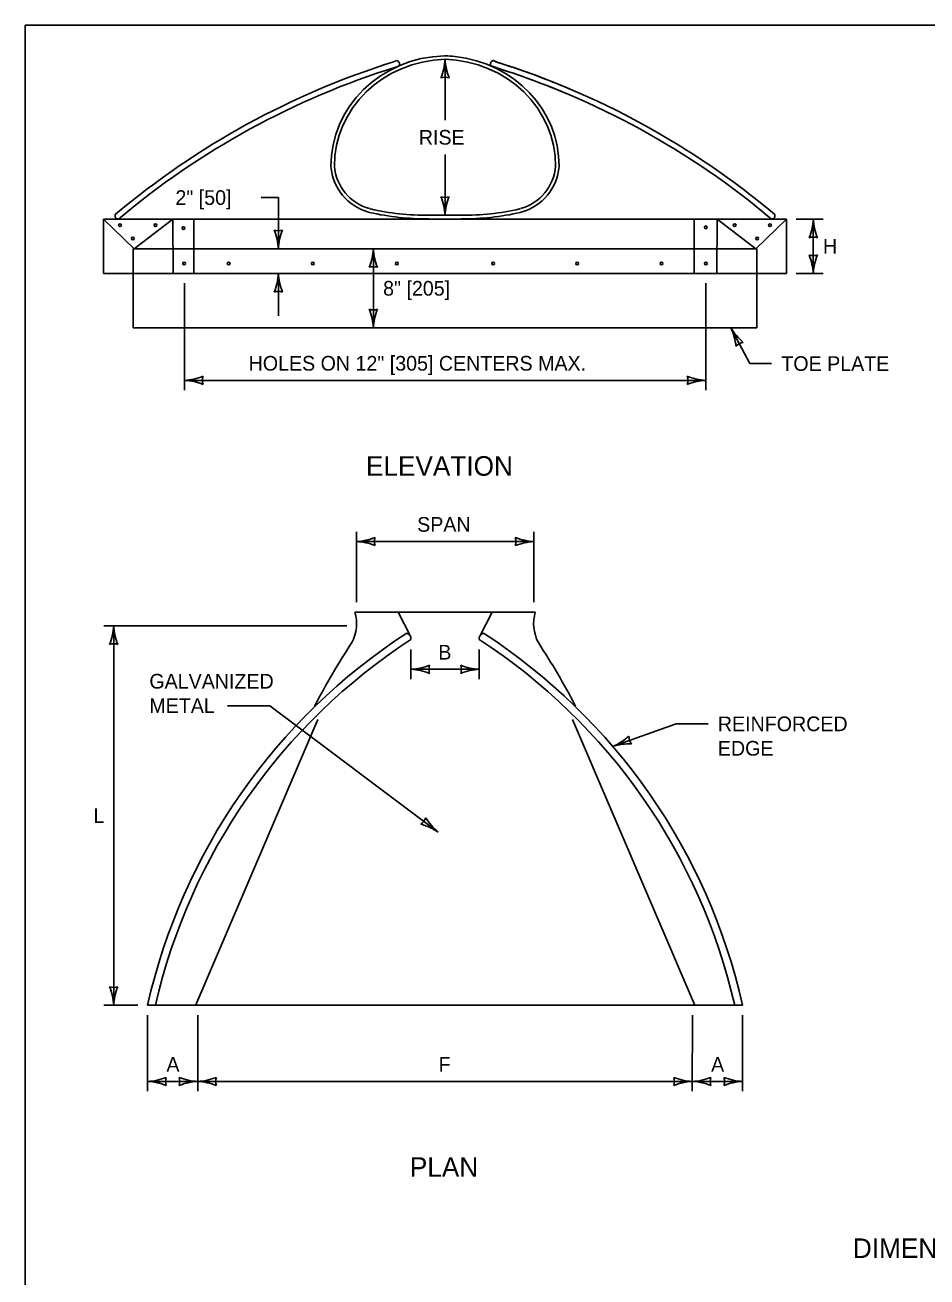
# Model space of a CAD drawing. Extents: x 49991.4 to 50021, y 49987.6 to 50011.4.
# Drawn here: x 49999.38 to 50003.07, y 49993.88 to 49999 of the extents above; entities that cross this region are included whole.
import ezdxf

# ---------------------------------------------------------------- set-up
doc = ezdxf.new("R2010")
doc.units = 0
for name, color, linetype in [('Level 1', 7, 'Continuous'), ('Level 2', 7, 'Continuous'), ('Level 3', 7, 'Continuous'), ('Level 4', 7, 'Continuous')]:
    doc.layers.add(name, color=color, linetype=linetype)

msp = doc.modelspace()

# ---------------------------------------------------------------- linework, layer by layer
at = {"layer": 'Level 1'}
for p, q in [((50000.8894, 49998.8486), (50000.9029, 49998.854)), ((50001.098, 49998.8735), (50001.1016, 49998.8735)), ((50001.3107, 49998.8483), (50001.2974, 49998.8541)), ((50001.3107, 49998.8483), (50001.2974, 49998.8541)), ((50001.3111, 49998.8483), (50001.298, 49998.8541)), ((50001.3111, 49998.8483), (50001.298, 49998.8541)), ((50000.8999, 49998.8274), (50000.9126, 49998.833)), ((50001.3008, 49998.8276), (50001.2877, 49998.833)), ((50001.3012, 49998.8276), (50001.2883, 49998.833)), ((50000.7879, 49998.2341), (50000.792, 49998.233)), ((50000.7924, 49998.2481), (50000.7965, 49998.2466)), ((50001.408, 49998.2481), (50001.404, 49998.2466)), ((50001.4122, 49998.2341), (50001.408, 49998.233)), ((49999.7044, 49997.9828), (49999.7044, 49998.2055)), ((49999.7044, 49998.2055), (50002.4958, 49998.2055)), ((49999.7044, 49998.2055), (49999.8291, 49998.0843)), ((49999.8291, 49998.0843), (49999.9875, 49998.2055)), ((49999.9875, 49998.2055), (49999.9887, 49997.9839)), ((50001.1005, 49998.221), (50001.0338, 49998.221)), ((50001.0341, 49998.207), (50001.1005, 49998.2055)), ((50001.6126, 49998.2055), (50001.0611, 49998.2055)), ((50001.1659, 49998.207), (50001.0999, 49998.2055)), ((50001.1005, 49998.221), (50001.1667, 49998.221)), ((50002.2128, 49998.2055), (50002.212, 49997.9839)), ((50002.3716, 49998.0843), (50002.2128, 49998.2055)), ((50002.4958, 49998.2055), (50002.3716, 49998.0843)), ((50002.4958, 49998.2055), (50002.4958, 49997.9828)), ((49999.7044, 49997.9828), (50002.4958, 49997.9828)), ((50001.1005, 49996.5982), (50000.7319, 49996.5982)), ((50000.9085, 49996.5982), (50000.9587, 49996.5001)), ((50001.1005, 49996.5982), (50001.4694, 49996.5982)), ((50001.293, 49996.5982), (50001.2424, 49996.5001)), ((50000.0815, 49994.9916), (50000.5799, 49996.1588)), ((50002.1208, 49994.9927), (50001.6209, 49996.1588)), ((49999.9163, 49994.9897), (49999.8846, 49994.9897)), ((50001.1005, 49994.9897), (49999.8846, 49994.9897)), ((50001.1005, 49994.9897), (50002.2845, 49994.9897)), ((50002.2854, 49994.9897), (50002.3169, 49994.9897))]:
    msp.add_line(p, q, dxfattribs=at)
msp.add_lwpolyline([(49999.3835, 49998.9992), (50016.7501, 49998.9992), (50016.7501, 49987.7988), (49999.3835, 49987.7988)], close=True, dxfattribs=at)
for centre in [(49999.7717, 49998.1811), (49999.9163, 49998.1811), (50002.1661, 49998.1718), (50002.2843, 49998.1811), (50002.4289, 49998.1811), (49999.8241, 49998.1265), (50000.031, 49998.1687), (50002.3766, 49998.1265), (50000.0338, 49998.0234), (50000.2158, 49998.0234), (50000.5597, 49998.0234), (50000.9036, 49998.0234), (50001.297, 49998.0234), (50001.6409, 49998.0234), (50001.9848, 49998.0234), (50002.1669, 49998.0234)]:
    msp.add_circle(centre, 0.00557, dxfattribs=at)
for centre, radius, start, end in [((50001.8796, 49995.6986), 3.3019, 107.4492, 130.0758), ((50000.8998, 49998.8398), 0.0145, 331.9431, 77.9332), ((50001.3006, 49998.8399), 0.0145, 102.0651, 208.4686), ((50001.3009, 49998.8399), 0.0145, 102.0651, 208.4686), ((50000.3179, 49995.6902), 3.3102, 66.9754, 72.6075), ((50000.3183, 49995.6902), 3.3102, 49.9808, 72.6075), ((50001.8821, 49995.6895), 3.2881, 107.3819, 130.0762), ((50000.3179, 49995.6902), 3.2878, 66.809, 72.6075), ((50000.3183, 49995.6902), 3.2878, 49.9128, 72.6075), ((50000.843, 49998.4366), 0.2097, 184.3908, 254.795), ((50000.843, 49998.4366), 0.1951, 184.3908, 254.795), ((50001.3576, 49998.4366), 0.1951, 285.205, 355.6092), ((50001.3573, 49998.4366), 0.2097, 285.205, 355.6092), ((50001.0191, 49999.2007), 0.994, 256.7971, 270.8603), ((50001.0191, 49999.2007), 0.9795, 256.7971, 270.8603), ((50001.1812, 49999.2007), 0.994, 269.1397, 283.2029), ((50001.1815, 49999.2007), 0.9795, 269.1397, 283.2029), ((49999.7647, 49998.2184), 0.0129, 148.2499, 272.1953), ((50002.4359, 49998.2184), 0.0129, 267.8624, 31.8078), ((50002.4359, 49998.2184), 0.0129, 267.8624, 31.8078), ((50000.5723, 49996.551), 0.1664, 332.1165, 16.4834), ((50001.6289, 49996.551), 0.1664, 163.5166, 207.8835), ((50002.2857, 49994.4484), 2.4616, 123.0384, 167.2954), ((50002.2857, 49994.4484), 2.4302, 123.0384, 167.1285), ((50000.9383, 49996.4897), 0.0228, 349.5581, 76.5269), ((50001.2628, 49996.4897), 0.0228, 103.4731, 190.4419), ((49999.9155, 49994.4484), 2.4302, 12.8715, 56.9616), ((49999.9155, 49994.4484), 2.4616, 12.7046, 56.9616), ((50003.3267, 49994.7722), 3.1131, 146.8806, 152.4206), ((49998.8745, 49994.7722), 3.1131, 27.5794, 33.1194)]:
    msp.add_arc(centre, radius, start, end, dxfattribs=at)
for centre, major_axis, ratio, start_param, end_param in [((50001.1136, 49998.4255), (-0.4797, -0.0049), 0.934337, 4.735052, 6.283185), ((50001.1136, 49998.4255), (-0.4651, -0.0047), 0.932282, 4.731472, 6.283185), ((50001.087, 49998.4255), (0.4651, -0.0047), 0.932282, 0, 1.551713), ((50001.0867, 49998.4255), (0.4797, -0.0049), 0.934337, 1.467761, 1.549044), ((50001.0867, 49998.4255), (0.4797, -0.0049), 0.934337, 0, 1.467761)]:
    msp.add_ellipse(centre, major_axis=major_axis, ratio=ratio, start_param=start_param, end_param=end_param, dxfattribs=at)
at = {"layer": 'Level 3'}
for p, q in [((50001.1005, 49998.8589), (50001.1005, 49998.61)), ((50001.1005, 49998.47), (50001.1005, 49998.221)), ((50000.4192, 49998.2935), (50000.3493, 49998.2935)), ((50000.4192, 49998.2935), (50000.4192, 49998.0842)), ((50002.5358, 49998.2055), (50002.6456, 49998.2055)), ((50002.6056, 49998.2055), (50002.6056, 49997.9828)), ((50000.8073, 49998.0842), (50000.8073, 49997.7607)), ((50000.4192, 49997.9828), (50000.4192, 49997.8094)), ((50002.5358, 49997.9828), (50002.6456, 49997.9828)), ((50000.0354, 49997.9428), (50000.0354, 49997.5057)), ((50002.1667, 49997.9428), (50002.1667, 49997.5057)), ((50002.3458, 49997.6145), (50002.2692, 49997.7607)), ((50002.3458, 49997.6145), (50002.4352, 49997.6145)), ((50000.0354, 49997.5457), (50002.1667, 49997.5457)), ((50000.7381, 49996.6382), (50000.7381, 49996.9266)), ((50001.4633, 49996.6382), (50001.4633, 49996.9266)), ((50000.7381, 49996.8866), (50001.4633, 49996.8866)), ((50000.6984, 49996.542), (49999.7058, 49996.542)), ((49999.7458, 49994.9897), (49999.7458, 49996.542)), ((50000.961, 49996.4456), (50000.961, 49996.3239)), ((50001.2405, 49996.4456), (50001.2405, 49996.3239)), ((50000.961, 49996.3639), (50001.2405, 49996.3639)), ((50000.2111, 49996.2152), (50000.3842, 49996.2152)), ((50001.0725, 49995.6977), (50000.3842, 49996.2152)), ((50002.0455, 49996.1409), (50001.7856, 49996.0489)), ((50002.0455, 49996.1409), (50002.1757, 49996.1409)), ((49999.8444, 49994.9897), (49999.7058, 49994.9897)), ((49999.8847, 49994.9497), (49999.8847, 49994.6381)), ((50000.0894, 49994.9497), (50000.0894, 49994.6381)), ((50002.1114, 49994.9497), (50002.1112, 49994.6381)), ((50002.3168, 49994.9497), (50002.3165, 49994.6381)), ((49999.8847, 49994.6781), (50000.0894, 49994.6781)), ((50000.0894, 49994.6781), (50000.0894, 49994.6781)), ((50000.0894, 49994.6781), (50002.1112, 49994.6781)), ((50002.1112, 49994.6781), (50002.3166, 49994.6781))]:
    msp.add_line(p, q, dxfattribs=at)
for centre, radius, start, end in [((50000.8784, 49998.8681), 0.2223, 337.456, 357.6395), ((50001.3333, 49998.8704), 0.233, 182.8273, 202.0772), ((50001.1005, 49998.7307), 0.0548, 72.1388, 107.8612), ((50001.1005, 49998.3492), 0.0548, 252.1388, 287.8612), ((50000.8678, 49998.2095), 0.233, 2.8273, 22.0772), ((50001.3227, 49998.2119), 0.2223, 157.456, 177.6395), ((50002.3835, 49998.2147), 0.2223, 337.456, 357.6395), ((50002.8384, 49998.217), 0.233, 182.8273, 202.0772), ((50000.4192, 49998.2124), 0.0548, 252.1388, 287.8612), ((50000.1865, 49998.0727), 0.233, 2.8273, 22.0772), ((50000.6414, 49998.0751), 0.2223, 157.456, 177.6395), ((50002.6056, 49998.0773), 0.0548, 72.1388, 107.8612), ((50000.5852, 49998.0934), 0.2223, 337.456, 357.6395), ((50001.0401, 49998.0957), 0.233, 182.8273, 202.0772), ((50002.6056, 49998.111), 0.0548, 252.1388, 287.8612), ((50002.3729, 49997.9713), 0.233, 2.8273, 22.0772), ((50002.8278, 49997.9737), 0.2223, 157.456, 177.6395), ((50000.1971, 49997.992), 0.2223, 337.456, 357.6395), ((50000.652, 49997.9943), 0.233, 182.8273, 202.0772), ((50000.8073, 49997.956), 0.0548, 72.1388, 107.8612), ((50000.4192, 49997.8546), 0.0548, 72.1388, 107.8612), ((50000.8073, 49997.8889), 0.0548, 252.1388, 287.8612), ((50000.5746, 49997.7492), 0.233, 2.8273, 22.0772), ((50001.0295, 49997.7516), 0.2223, 157.456, 177.6395), ((50002.0682, 49997.6657), 0.2223, 5.1078, 25.2914), ((50002.47, 49997.8789), 0.233, 210.4791, 229.729), ((50002.3287, 49997.6471), 0.0548, 99.7907, 135.513), ((50000.0239, 49997.7784), 0.233, 272.8273, 292.0772), ((50000.1637, 49997.5457), 0.0548, 162.1388, 197.8612), ((50002.1759, 49997.7678), 0.2223, 247.456, 267.6395), ((50002.0385, 49997.5457), 0.0548, 342.1388, 17.8612), ((50000.0263, 49997.3236), 0.2223, 67.456, 87.6395), ((50002.1782, 49997.313), 0.233, 92.8273, 112.0772), ((50000.7266, 49997.1193), 0.233, 272.8273, 292.0772), ((50000.8664, 49996.8866), 0.0548, 162.1388, 197.8612), ((50001.4725, 49997.1088), 0.2223, 247.456, 267.6395), ((50001.3351, 49996.8866), 0.0548, 342.1388, 17.8612), ((50000.729, 49996.6645), 0.2223, 67.456, 87.6395), ((50001.4748, 49996.6539), 0.233, 92.8273, 112.0772), ((49999.5237, 49996.5512), 0.2223, 337.456, 357.6395), ((49999.9786, 49996.5535), 0.233, 182.8273, 202.0772), ((49999.7458, 49996.4138), 0.0548, 72.1388, 107.8612), ((50000.9495, 49996.5966), 0.233, 272.8273, 292.0772), ((50000.9519, 49996.1418), 0.2223, 67.456, 87.6395), ((50001.0893, 49996.3639), 0.0548, 162.1388, 197.8612), ((50001.2497, 49996.5861), 0.2223, 247.456, 267.6395), ((50001.1123, 49996.3639), 0.0548, 342.1388, 17.8612), ((50001.252, 49996.1312), 0.233, 92.8273, 112.0772), ((50001.6971, 49996.2644), 0.233, 292.3235, 311.5734), ((50001.9065, 49996.0917), 0.0548, 181.6351, 217.3574), ((50001.8512, 49995.8365), 0.2223, 86.9522, 107.1358), ((50000.9701, 49995.7748), 0.0548, 305.2011, 340.9234), ((50000.9419, 49995.5048), 0.233, 55.8895, 75.1394), ((50001.2133, 49995.8698), 0.2223, 210.5182, 230.7018), ((49999.7458, 49995.1179), 0.0548, 252.1388, 287.8612), ((49999.5131, 49994.9782), 0.233, 2.8273, 22.0772), ((49999.968, 49994.9806), 0.2223, 157.456, 177.6395), ((49999.8732, 49994.9108), 0.233, 272.8273, 292.0772), ((50000.013, 49994.6781), 0.0548, 162.1388, 197.8612), ((50000.0986, 49994.9003), 0.2223, 247.456, 267.6395), ((49999.9612, 49994.6781), 0.0548, 342.1388, 17.8612), ((50000.0779, 49994.9108), 0.233, 272.8273, 292.0772), ((50000.2177, 49994.6781), 0.0548, 162.1388, 197.8612), ((50002.1204, 49994.9003), 0.2223, 247.456, 267.6395), ((50001.9831, 49994.6781), 0.0548, 342.1388, 17.8612), ((50002.0998, 49994.9108), 0.233, 272.8273, 292.0772), ((50002.2395, 49994.6781), 0.0548, 162.1388, 197.8612), ((50002.3257, 49994.9003), 0.2223, 247.456, 267.6395), ((50002.1884, 49994.6781), 0.0548, 342.1388, 17.8612), ((49999.8756, 49994.456), 0.2223, 67.456, 87.6395), ((50000.1009, 49994.4454), 0.233, 92.8273, 112.0772), ((50000.0803, 49994.456), 0.2223, 67.456, 87.6395), ((50002.1228, 49994.4454), 0.233, 92.8273, 112.0772), ((50002.1021, 49994.456), 0.2223, 67.456, 87.6395), ((50002.3281, 49994.4454), 0.233, 92.8273, 112.0772)]:
    msp.add_arc(centre, radius, start, end, dxfattribs=at)
at = {"layer": 'Level 4'}
for p, q in [((50000.073, 49998.2045), (50000.0736, 49997.9837)), ((50002.1188, 49998.2045), (50002.1194, 49997.9837)), ((49999.8256, 49997.7607), (49999.8256, 49998.0842)), ((49999.8256, 49998.0842), (50002.3746, 49998.0842)), ((50002.3746, 49997.7607), (50002.3746, 49998.0842)), ((49999.8256, 49997.7607), (50002.3746, 49997.7607))]:
    msp.add_line(p, q, dxfattribs=at)

# ---------------------------------------------------------------- texts
at = {"layer": 'Level 2'}
for s, height, p in [('RISE', 0.06, (50000.9933, 49998.51)), ('2" [50]', 0.06, (49999.9982, 49998.2635)), ('H', 0.06, (50002.6456, 49998.0642)), ('8" [205]', 0.06, (50000.8473, 49997.8924)), ('HOLES ON 12" [305] CENTERS MAX.', 0.06, (50000.2975, 49997.5857)), ('TOE PLATE', 0.06, (50002.4752, 49997.5845)), ('ELEVATION', 0.08, (50000.7773, 49997.1557)), ('SPAN', 0.06, (50000.9864, 49996.9266)), ('B', 0.06, (50001.073, 49996.4039)), ('GALVANIZED', 0.06, (49999.8917, 49996.2852)), ('METAL', 0.06, (49999.8917, 49996.1852)), ('REINFORCED', 0.06, (50002.2157, 49996.1109)), ('EDGE', 0.06, (50002.2157, 49996.0109)), ('L', 0.06, (49999.6635, 49995.7358)), ('A', 0.06, (49999.9613, 49994.7181)), ('F', 0.06, (50001.0742, 49994.7181)), ('A', 0.06, (50002.1881, 49994.7181)), ('PLAN', 0.08, (50000.9566, 49994.2881)), ('DIMENSION TABLE', 0.08, (50002.7677, 49993.9561))]:
    msp.add_text(s, height=height, dxfattribs=at).set_placement(p)

doc.saveas('drawing.dxf')
